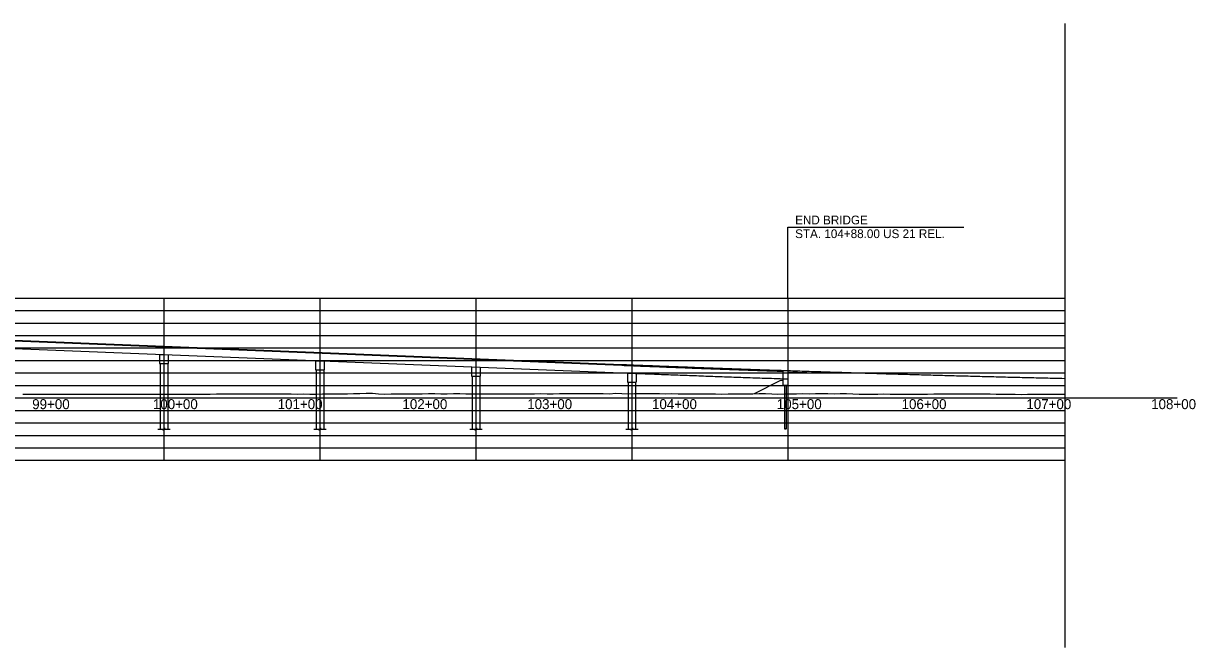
# Model space of a CAD drawing. Extents: x -464 to 4306, y -1372 to 300.
# Drawn here: x 3105 to 4044, y -200 to 300 of the extents above; entities that cross this region are included whole.
import ezdxf

# ---------------------------------------------------------------- set-up
doc = ezdxf.new("R2010")
doc.units = 0
for name, color, linetype in [('BR_AUTO DIMENSION', 7, 'Continuous'), ('BR_GRID LINES', 7, 'Continuous'), ('Default', 7, 'Continuous'), ('Mis Ground Lines', 7, 'Continuous'), ('Miscellaneous Lines', 7, 'Continuous'), ('NOPLOT', 7, 'Continuous'), ('sub interior bent cap lines', 7, 'Continuous'), ('Sub Interior Bent Footing Line', 7, 'Continuous'), ('Sub Steel Pile Lines', 7, 'Continuous'), ('Sup Concrete Girder Lines', 7, 'Continuous'), ('Sup Concrete Slab Lines', 7, 'Continuous')]:
    doc.layers.add(name, color=color, linetype=linetype)

msp = doc.modelspace()

# ---------------------------------------------------------------- linework, layer by layer
at = {"layer": 'BR_AUTO DIMENSION'}
for points in [[(3212.8, -25), (3217.11, -25), (3217.11, -26.12), (3218.23, -23.88), (3218.23, -25), (3222.55, -25)], [(3337.8, -25), (3342.11, -25), (3342.11, -26.12), (3343.23, -23.88), (3343.23, -25), (3347.55, -25)], [(3462.8, -25), (3467.11, -25), (3467.11, -26.12), (3468.23, -23.88), (3468.23, -25), (3472.55, -25)], [(3587.8, -25), (3592.11, -25), (3592.11, -26.12), (3593.23, -23.88), (3593.23, -25), (3597.55, -25)], [(3716.53, -24.89), (3715.83, -24.89), (3715.83, -25.21), (3715.51, -24.57), (3715.51, -24.89), (3714.81, -24.89)]]:
    msp.add_lwpolyline(points, dxfattribs=at)
at = {"layer": 'BR_GRID LINES'}
for p, q in [((3939.67, 300), (3939.67, -200)), ((-80.33, 80), (3939.67, 80)), ((-80.33, 70), (3939.67, 70)), ((-80.33, 60), (3939.67, 60)), ((-80.33, 50), (3939.67, 50)), ((-80.33, 40), (3939.67, 40)), ((-80.33, 30), (3939.67, 30)), ((-80.33, 20), (3939.67, 20)), ((-80.33, 10), (3939.67, 10)), ((-80.33, 0), (3939.67, 0)), ((-80.33, -10), (3939.67, -10)), ((-80.33, -20), (3939.67, -20)), ((-80.33, -30), (3939.67, -30)), ((-80.33, -40), (3939.67, -40)), ((-80.33, -50), (3939.67, -50))]:
    msp.add_line(p, q, dxfattribs=at)
at = {"layer": 'Default'}
for p, q in [((3217.67, 80), (3217.67, -50)), ((3342.67, 80), (3342.67, -50)), ((3467.67, 80), (3467.67, -50)), ((3592.67, 80), (3592.67, -50)), ((3717.67, 80), (3717.67, -50)), ((-170.33, 0), (4029.67, 0))]:
    msp.add_line(p, q, dxfattribs=at)
at = {"layer": 'Mis Ground Lines'}
for p, q in [((3711.67, 13.91), (3690.61, 3.38)), ((3713.67, 13.91), (3711.67, 13.91)), ((3929.67, 3.01), (3934.67, 2.97)), ((3934.67, 2.97), (3939.67, 3.04))]:
    msp.add_line(p, q, dxfattribs=at)
for points in [[(3104.67, 3.04), (3109.67, 3.01), (3114.67, 3.03), (3119.67, 3.06), (3124.67, 2.99), (3129.67, 3.09), (3134.67, 3.1), (3139.67, 3.06), (3144.67, 3.01), (3149.67, 2.97), (3154.67, 2.97), (3159.67, 2.98), (3164.67, 3.01), (3169.67, 3.04), (3174.67, 3.04), (3179.67, 3.01), (3184.67, 3.03), (3189.67, 3), (3194.67, 3), (3199.67, 3), (3204.67, 3.01), (3209.67, 3.06), (3214.67, 3.03), (3219.67, 2.99), (3224.67, 3.03), (3229.67, 3.06)], [(3229.67, 3.06), (3234.67, 3.05), (3239.67, 3.01), (3244.67, 3.03), (3249.67, 3.07), (3254.67, 3.11), (3259.67, 3.18), (3264.67, 3.21), (3269.67, 3.21), (3274.67, 3.15), (3279.67, 3.16), (3284.67, 3.16), (3289.67, 3.2), (3294.67, 3.17), (3299.67, 3.18), (3304.67, 3.19), (3309.67, 3.18), (3314.67, 3.18), (3319.67, 3.16), (3324.67, 3.13), (3329.67, 3.22), (3334.67, 3.13), (3339.67, 3.12), (3344.67, 3.17), (3349.67, 3.22), (3354.67, 3.29), (3359.67, 3.25), (3364.67, 3.29), (3369.67, 3.5), (3374.67, 3.61), (3379.67, 3.76), (3384.67, 3.68), (3389.67, 3.17), (3394.67, 3.09), (3399.67, 3.14), (3404.67, 3.19), (3409.67, 3.26), (3414.67, 3.27), (3419.67, 3.28), (3424.67, 3.38), (3429.67, 3.48), (3434.67, 3.5), (3439.67, 3.35), (3444.67, 3.37), (3449.67, 3.59), (3454.67, 3.4), (3459.67, 3.28), (3464.67, 3.24), (3469.67, 3.26), (3474.67, 3.2), (3479.67, 3.23), (3484.67, 3.32), (3489.67, 3.37), (3494.67, 3.36), (3499.67, 3.28), (3504.67, 3.17), (3509.67, 3.18), (3514.67, 3.29), (3519.67, 3.45), (3524.67, 3.33), (3529.67, 3.37), (3534.67, 3.54), (3539.67, 3.43), (3544.67, 3.6), (3549.67, 3.54), (3554.67, 3.52), (3559.67, 3.59), (3564.67, 3.52), (3569.67, 3.58), (3574.67, 3.38), (3579.67, 3.67), (3584.67, 3.59), (3589.67, 3.39), (3594.67, 3.54), (3599.67, 3.56), (3604.67, 3.58), (3609.67, 3.59), (3614.67, 3.51), (3619.67, 3.39), (3624.67, 3.47), (3629.67, 3.23), (3634.67, 3.35), (3639.67, 3.35), (3644.67, 3.36), (3649.67, 3.28), (3654.67, 3.3), (3659.67, 3.17), (3664.67, 3.12), (3669.67, 3.2), (3674.67, 3.24), (3679.67, 3.21), (3684.67, 3.17), (3689.67, 3.35), (3694.67, 3.5), (3699.67, 3.55), (3704.67, 3.15), (3709.67, 3.09), (3714.67, 3.21), (3719.67, 3.18), (3724.67, 3.26), (3729.67, 3.47)], [(3729.67, 3.47), (3734.67, 3.39), (3739.67, 3.48), (3744.67, 3.53), (3749.67, 3.4), (3754.67, 3.34), (3759.67, 3.5), (3764.67, 3.46), (3769.67, 3.14), (3774.67, 3.13), (3779.67, 3.12), (3784.67, 3.12), (3789.67, 3.1), (3794.67, 3.17), (3799.67, 3.09), (3804.67, 3.04), (3809.67, 3.02), (3814.67, 2.98), (3819.67, 2.99), (3824.67, 3.12), (3829.67, 3.1), (3834.67, 3.21), (3839.67, 3.26), (3844.67, 3.25), (3849.67, 3.28), (3854.67, 3.14), (3859.67, 3.31), (3864.67, 3.22), (3869.67, 3.16), (3874.67, 3.17), (3879.67, 3.2), (3884.67, 3.13), (3889.67, 3.05), (3894.67, 3.02), (3899.67, 2.97), (3904.67, 2.86), (3909.67, 2.92), (3914.67, 2.95), (3919.67, 2.98), (3924.67, 3.02), (3929.67, 3.01)]]:
    msp.add_lwpolyline(points, dxfattribs=at)
at = {"layer": 'Miscellaneous Lines'}
msp.add_line((3737.67, 21.25), (3737.67, 20.08), dxfattribs=at)
msp.add_spline([(3717.67, 20.74), (3719.63, 20.68), (3734.63, 20.18), (3737.67, 20.08)], degree=3, dxfattribs=at)
at = {"layer": 'NOPLOT'}
for p, q in [((3717.67, 136.81), (3858.58, 136.81)), ((3717.67, 80), (3717.67, 136.81))]:
    msp.add_line(p, q, dxfattribs=at)
at = {"layer": 'sub interior bent cap lines'}
for p, q in [((3214.17, 34.61), (3214.17, 27.47)), ((3221.17, 34.33), (3214.17, 34.61)), ((3221.17, 34.33), (3221.17, 27.47)), ((3339.17, 29.61), (3339.17, 22.47)), ((3339.17, 29.61), (3346.17, 29.33)), ((3346.17, 29.33), (3346.17, 22.47)), ((3214.17, 27.47), (3221.17, 27.47)), ((3214.67, 27.47), (3214.67, -25)), ((3220.67, 27.47), (3220.67, -25)), ((3339.17, 22.47), (3346.17, 22.47)), ((3339.67, 22.47), (3339.67, -25)), ((3345.67, 22.47), (3345.67, -25)), ((3464.17, 24.61), (3464.17, 17.47)), ((3471.17, 24.33), (3464.17, 24.61)), ((3471.17, 24.33), (3471.17, 17.47)), ((3589.17, 19.62), (3589.17, 12.48)), ((3596.17, 19.34), (3589.17, 19.62)), ((3596.17, 19.34), (3596.17, 12.48)), ((3464.17, 17.47), (3471.17, 17.47)), ((3464.67, 17.47), (3464.67, -25)), ((3470.67, 17.47), (3470.67, -25)), ((3589.17, 12.48), (3596.17, 12.48)), ((3589.67, 12.48), (3589.67, -25)), ((3595.67, 12.48), (3595.67, -25))]:
    msp.add_line(p, q, dxfattribs=at)
at = {"layer": 'Sub Interior Bent Footing Line'}
for p, q in [((3713.67, 22.04), (3713.67, 9.91)), ((3717.67, 21.91), (3717.67, 9.91)), ((3717.67, 14.91), (3713.67, 14.91)), ((3717.67, 9.91), (3713.67, 9.91))]:
    msp.add_line(p, q, dxfattribs=at)
at = {"layer": 'Sub Steel Pile Lines'}
for p, q in [((3715.06, 9.91), (3715.06, -24.89)), ((3716.28, 9.91), (3716.28, -24.89))]:
    msp.add_line(p, q, dxfattribs=at)
at = {"layer": 'Sup Concrete Girder Lines'}
for p, q in [((2634.41, 58.14), (3584.41, 20.14)), ((2634.65, 64.13), (3584.65, 26.13))]:
    msp.add_line(p, q, dxfattribs=at)
for points in [[(3584.41, 20.14), (3599.41, 19.54), (3614.42, 18.96), (3629.42, 18.39), (3644.42, 17.83), (3659.43, 17.27), (3674.43, 16.73), (3689.44, 16.2), (3704.44, 15.69), (3713.67, 15.37)], [(3584.65, 26.13), (3599.65, 25.54), (3614.65, 24.96), (3629.65, 24.38), (3644.65, 23.82), (3659.65, 23.27), (3674.65, 22.73), (3689.65, 22.2), (3704.65, 21.68), (3713.67, 21.38)]]:
    msp.add_spline(points, degree=3, dxfattribs=at)
at = {"layer": 'Sup Concrete Slab Lines'}
msp.add_line((2634.67, 64.8), (3584.67, 26.8), dxfattribs=at)
msp.add_spline([(3584.67, 26.8), (3599.67, 26.21), (3614.67, 25.62), (3629.67, 25.05), (3644.67, 24.49), (3659.67, 23.94), (3674.67, 23.4), (3689.67, 22.87), (3704.67, 22.35), (3719.67, 21.84), (3734.67, 21.34), (3749.67, 20.86), (3764.67, 20.38), (3779.67, 19.92), (3794.67, 19.47), (3809.67, 19.03), (3824.67, 18.6), (3839.67, 18.17), (3854.67, 17.77), (3869.67, 17.37), (3884.67, 16.98), (3899.67, 16.6), (3914.67, 16.24), (3929.67, 15.88), (3939.67, 15.65)], degree=3, dxfattribs=at)

# ---------------------------------------------------------------- texts
at = {"layer": 'NOPLOT'}
for s, height, p in [('END BRIDGE', 7, (3723.47, 139.04)), ('STA. 104+88.00 US 21 REL.', 7, (3723.47, 128.04)), ('99+00', 8, (3112.08, -9)), ('100+00', 8, (3208.77, -9)), ('101+00', 8, (3308.77, -9)), ('102+00', 8, (3408.77, -9)), ('103+00', 8, (3508.77, -9)), ('104+00', 8, (3608.77, -9)), ('105+00', 8, (3708.77, -9)), ('106+00', 8, (3808.77, -9)), ('107+00', 8, (3908.77, -9)), ('108+00', 8, (4008.77, -9))]:
    msp.add_text(s, height=height, dxfattribs=at).set_placement(p)

doc.saveas('drawing.dxf')
